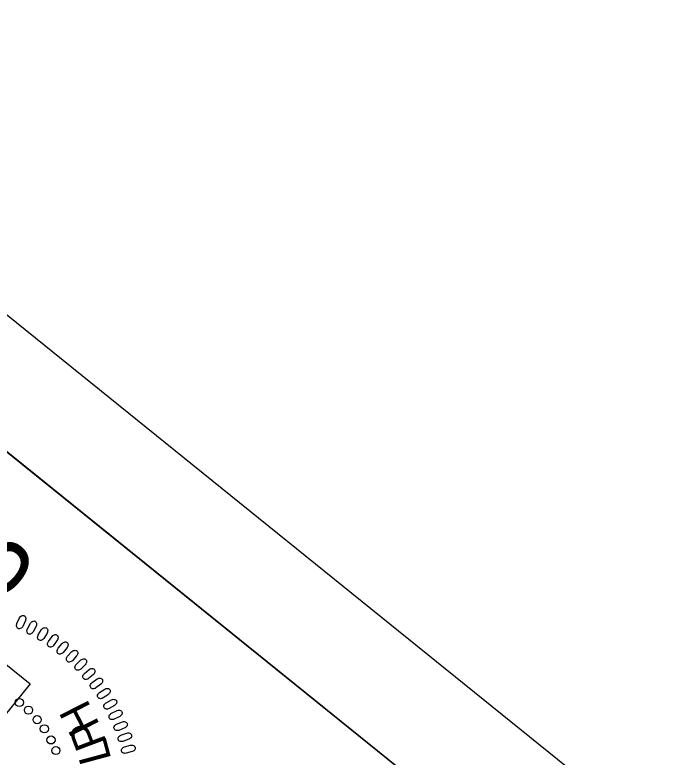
# Model space of a CAD drawing. Extents: x 1487832 to 1490056, y 498345 to 500343.
# Drawn here: x 1488992.8 to 1489096.2, y 500224.6 to 500343.2 of the extents above; entities that cross this region are included whole.
import ezdxf

# ---------------------------------------------------------------- set-up
doc = ezdxf.new("R2010")
doc.units = 0
for name, color, linetype in [('Old_Level_9', 7, 'Continuous'), ('Sheet Plan CELL', 7, 'Continuous'), ('Sheet Plot Border Outside CELL', 7, 'Continuous'), ('Sheet Sticker Incomplete CELL', 7, 'Continuous')]:
    doc.layers.add(name, color=color, linetype=linetype)

msp = doc.modelspace()

# ---------------------------------------------------------------- linework, layer by layer
at = {"layer": 'Old_Level_9'}
for points in [[(1488993.11, 500245.93), (1488993.52, 500246.83), (1488993.62, 500246.98), (1488993.71, 500247.07), (1488993.85, 500247.15), (1488993.96, 500247.2), (1488994.07, 500247.22), (1488994.16, 500247.22), (1488994.25, 500247.2), (1488994.32, 500247.14), (1488994.4, 500247.08), (1488994.46, 500247), (1488994.5, 500246.89), (1488994.52, 500246.81), (1488994.52, 500246.68), (1488994.5, 500246.53), (1488994.47, 500246.4), (1488994.05, 500245.47), (1488993.98, 500245.36), (1488993.9, 500245.27), (1488993.78, 500245.18), (1488993.65, 500245.12), (1488993.55, 500245.09), (1488993.41, 500245.1), (1488993.3, 500245.13), (1488993.2, 500245.21), (1488993.14, 500245.29), (1488993.08, 500245.4), (1488993.05, 500245.57), (1488993.06, 500245.72), (1488993.08, 500245.83)], [(1488994.79, 500245.1), (1488995.26, 500245.98), (1488995.37, 500246.12), (1488995.46, 500246.2), (1488995.61, 500246.28), (1488995.72, 500246.32), (1488995.83, 500246.34), (1488995.92, 500246.33), (1488996.01, 500246.3), (1488996.08, 500246.24), (1488996.15, 500246.17), (1488996.2, 500246.09), (1488996.24, 500245.98), (1488996.25, 500245.9), (1488996.24, 500245.77), (1488996.22, 500245.62), (1488996.17, 500245.49), (1488995.7, 500244.59), (1488995.62, 500244.48), (1488995.53, 500244.4), (1488995.41, 500244.32), (1488995.28, 500244.26), (1488995.18, 500244.24), (1488995.04, 500244.26), (1488994.93, 500244.3), (1488994.83, 500244.39), (1488994.78, 500244.46), (1488994.73, 500244.58), (1488994.71, 500244.75), (1488994.73, 500244.9), (1488994.75, 500245.01)], [(1488996.53, 500244.12), (1488997.06, 500244.96), (1488997.17, 500245.1), (1488997.27, 500245.17), (1488997.42, 500245.24), (1488997.53, 500245.27), (1488997.64, 500245.28), (1488997.73, 500245.26), (1488997.82, 500245.23), (1488997.89, 500245.17), (1488997.96, 500245.1), (1488998, 500245.01), (1488998.03, 500244.9), (1488998.04, 500244.82), (1488998.02, 500244.69), (1488997.99, 500244.54), (1488997.94, 500244.42), (1488997.41, 500243.55), (1488997.32, 500243.44), (1488997.23, 500243.36), (1488997.1, 500243.29), (1488996.96, 500243.24), (1488996.86, 500243.23), (1488996.73, 500243.25), (1488996.62, 500243.31), (1488996.53, 500243.4), (1488996.48, 500243.47), (1488996.43, 500243.6), (1488996.42, 500243.77), (1488996.45, 500243.92), (1488996.49, 500244.02)], [(1488998.15, 500243.07), (1488998.72, 500243.88), (1488998.85, 500244.01), (1488998.95, 500244.07), (1488999.1, 500244.13), (1488999.22, 500244.16), (1488999.33, 500244.16), (1488999.42, 500244.14), (1488999.5, 500244.1), (1488999.57, 500244.03), (1488999.63, 500243.96), (1488999.67, 500243.87), (1488999.7, 500243.75), (1488999.7, 500243.67), (1488999.67, 500243.54), (1488999.63, 500243.4), (1488999.57, 500243.28), (1488998.98, 500242.45), (1488998.89, 500242.34), (1488998.79, 500242.27), (1488998.66, 500242.21), (1488998.52, 500242.17), (1488998.42, 500242.16), (1488998.29, 500242.2), (1488998.18, 500242.25), (1488998.1, 500242.35), (1488998.05, 500242.43), (1488998.02, 500242.56), (1488998.02, 500242.72), (1488998.06, 500242.87), (1488998.1, 500242.97)], [(1488999.69, 500241.98), (1489000.32, 500242.75), (1489000.45, 500242.87), (1489000.56, 500242.93), (1489000.71, 500242.98), (1489000.83, 500243), (1489000.94, 500242.99), (1489001.03, 500242.97), (1489001.11, 500242.92), (1489001.17, 500242.85), (1489001.23, 500242.77), (1489001.27, 500242.68), (1489001.28, 500242.56), (1489001.28, 500242.48), (1489001.24, 500242.36), (1489001.19, 500242.21), (1489001.12, 500242.1), (1489000.49, 500241.3), (1489000.39, 500241.21), (1489000.29, 500241.14), (1489000.15, 500241.09), (1489000.01, 500241.06), (1488999.91, 500241.06), (1488999.78, 500241.1), (1488999.67, 500241.16), (1488999.6, 500241.26), (1488999.56, 500241.35), (1488999.53, 500241.48), (1488999.54, 500241.64), (1488999.59, 500241.79), (1488999.64, 500241.89)], [(1489001.22, 500240.72), (1489001.89, 500241.45), (1489002.03, 500241.56), (1489002.14, 500241.61), (1489002.3, 500241.65), (1489002.42, 500241.67), (1489002.53, 500241.65), (1489002.61, 500241.62), (1489002.69, 500241.57), (1489002.74, 500241.5), (1489002.8, 500241.41), (1489002.83, 500241.32), (1489002.84, 500241.2), (1489002.83, 500241.12), (1489002.79, 500241), (1489002.72, 500240.86), (1489002.65, 500240.75), (1489001.97, 500239.99), (1489001.86, 500239.91), (1489001.76, 500239.85), (1489001.62, 500239.8), (1489001.47, 500239.78), (1489001.37, 500239.78), (1489001.25, 500239.83), (1489001.15, 500239.9), (1489001.08, 500240.01), (1489001.04, 500240.1), (1489001.02, 500240.23), (1489001.04, 500240.39), (1489001.1, 500240.54), (1489001.15, 500240.63)], [(1489002.61, 500239.42), (1489003.32, 500240.11), (1489003.47, 500240.21), (1489003.58, 500240.26), (1489003.75, 500240.29), (1489003.86, 500240.29), (1489003.97, 500240.27), (1489004.05, 500240.24), (1489004.13, 500240.18), (1489004.18, 500240.1), (1489004.23, 500240.02), (1489004.25, 500239.92), (1489004.26, 500239.81), (1489004.24, 500239.73), (1489004.19, 500239.6), (1489004.12, 500239.47), (1489004.04, 500239.36), (1489003.31, 500238.65), (1489003.2, 500238.57), (1489003.09, 500238.52), (1489002.95, 500238.48), (1489002.81, 500238.47), (1489002.7, 500238.48), (1489002.58, 500238.54), (1489002.49, 500238.62), (1489002.43, 500238.73), (1489002.4, 500238.81), (1489002.38, 500238.94), (1489002.41, 500239.11), (1489002.48, 500239.25), (1489002.54, 500239.34)], [(1489003.91, 500237.96), (1489004.67, 500238.6), (1489004.82, 500238.69), (1489004.94, 500238.73), (1489005.1, 500238.75), (1489005.22, 500238.75), (1489005.33, 500238.72), (1489005.41, 500238.68), (1489005.48, 500238.62), (1489005.52, 500238.54), (1489005.57, 500238.45), (1489005.59, 500238.35), (1489005.58, 500238.24), (1489005.56, 500238.16), (1489005.51, 500238.04), (1489005.43, 500237.91), (1489005.34, 500237.81), (1489004.57, 500237.15), (1489004.45, 500237.07), (1489004.34, 500237.03), (1489004.19, 500237), (1489004.05, 500237), (1489003.95, 500237.01), (1489003.83, 500237.08), (1489003.74, 500237.16), (1489003.69, 500237.27), (1489003.66, 500237.36), (1489003.66, 500237.5), (1489003.7, 500237.66), (1489003.77, 500237.79), (1489003.84, 500237.88)], [(1489005.12, 500236.49), (1489005.91, 500237.08), (1489006.07, 500237.16), (1489006.19, 500237.2), (1489006.35, 500237.2), (1489006.47, 500237.19), (1489006.58, 500237.16), (1489006.65, 500237.11), (1489006.72, 500237.05), (1489006.76, 500236.97), (1489006.8, 500236.87), (1489006.81, 500236.78), (1489006.8, 500236.66), (1489006.78, 500236.58), (1489006.71, 500236.47), (1489006.62, 500236.34), (1489006.53, 500236.25), (1489005.72, 500235.64), (1489005.6, 500235.57), (1489005.49, 500235.53), (1489005.34, 500235.51), (1489005.19, 500235.52), (1489005.1, 500235.54), (1489004.98, 500235.61), (1489004.9, 500235.7), (1489004.85, 500235.82), (1489004.83, 500235.91), (1489004.83, 500236.04), (1489004.89, 500236.2), (1489004.97, 500236.33), (1489005.04, 500236.41)], [(1489006.32, 500234.92), (1489007.15, 500235.46), (1489007.32, 500235.54), (1489007.43, 500235.56), (1489007.6, 500235.56), (1489007.72, 500235.54), (1489007.82, 500235.5), (1489007.89, 500235.45), (1489007.96, 500235.38), (1489007.99, 500235.3), (1489008.02, 500235.2), (1489008.03, 500235.11), (1489008.01, 500234.99), (1489007.98, 500234.91), (1489007.91, 500234.8), (1489007.81, 500234.68), (1489007.72, 500234.6), (1489006.87, 500234.04), (1489006.74, 500233.98), (1489006.63, 500233.94), (1489006.48, 500233.93), (1489006.34, 500233.95), (1489006.24, 500233.98), (1489006.13, 500234.06), (1489006.05, 500234.15), (1489006.01, 500234.27), (1489006, 500234.36), (1489006.01, 500234.5), (1489006.07, 500234.65), (1489006.16, 500234.78), (1489006.24, 500234.85)], [(1489007.35, 500233.26), (1489008.21, 500233.75), (1489008.38, 500233.81), (1489008.5, 500233.83), (1489008.67, 500233.82), (1489008.78, 500233.79), (1489008.88, 500233.74), (1489008.95, 500233.69), (1489009.01, 500233.62), (1489009.04, 500233.53), (1489009.07, 500233.43), (1489009.07, 500233.33), (1489009.04, 500233.22), (1489009.01, 500233.15), (1489008.93, 500233.04), (1489008.83, 500232.93), (1489008.72, 500232.85), (1489007.84, 500232.34), (1489007.71, 500232.29), (1489007.59, 500232.26), (1489007.45, 500232.26), (1489007.3, 500232.29), (1489007.21, 500232.32), (1489007.1, 500232.41), (1489007.03, 500232.51), (1489007, 500232.63), (1489006.99, 500232.72), (1489007.01, 500232.85), (1489007.08, 500233), (1489007.18, 500233.12), (1489007.26, 500233.2)], [(1489008.21, 500231.6), (1489009.11, 500232.03), (1489009.28, 500232.08), (1489009.4, 500232.1), (1489009.56, 500232.07), (1489009.68, 500232.04), (1489009.78, 500231.99), (1489009.84, 500231.93), (1489009.9, 500231.85), (1489009.92, 500231.76), (1489009.94, 500231.67), (1489009.94, 500231.57), (1489009.9, 500231.46), (1489009.86, 500231.39), (1489009.78, 500231.28), (1489009.67, 500231.18), (1489009.56, 500231.1), (1489008.65, 500230.65), (1489008.52, 500230.61), (1489008.4, 500230.59), (1489008.25, 500230.6), (1489008.11, 500230.63), (1489008.02, 500230.68), (1489007.92, 500230.77), (1489007.85, 500230.87), (1489007.83, 500230.99), (1489007.83, 500231.09), (1489007.85, 500231.22), (1489007.93, 500231.36), (1489008.04, 500231.48), (1489008.13, 500231.54)], [(1489009.04, 500229.85), (1489009.96, 500230.22), (1489010.13, 500230.26), (1489010.25, 500230.27), (1489010.41, 500230.24), (1489010.53, 500230.2), (1489010.62, 500230.14), (1489010.68, 500230.07), (1489010.73, 500229.99), (1489010.75, 500229.9), (1489010.76, 500229.8), (1489010.75, 500229.71), (1489010.71, 500229.6), (1489010.67, 500229.53), (1489010.58, 500229.43), (1489010.46, 500229.33), (1489010.35, 500229.27), (1489009.41, 500228.87), (1489009.28, 500228.84), (1489009.16, 500228.83), (1489009.01, 500228.85), (1489008.87, 500228.89), (1489008.78, 500228.94), (1489008.69, 500229.04), (1489008.63, 500229.14), (1489008.61, 500229.27), (1489008.62, 500229.36), (1489008.65, 500229.49), (1489008.74, 500229.63), (1489008.86, 500229.73), (1489008.94, 500229.8)], [(1489009.73, 500228.11), (1489010.67, 500228.43), (1489010.85, 500228.45), (1489010.97, 500228.45), (1489011.13, 500228.41), (1489011.24, 500228.36), (1489011.33, 500228.3), (1489011.38, 500228.23), (1489011.43, 500228.15), (1489011.44, 500228.06), (1489011.45, 500227.96), (1489011.43, 500227.86), (1489011.38, 500227.75), (1489011.34, 500227.69), (1489011.24, 500227.6), (1489011.12, 500227.5), (1489011, 500227.45), (1489010.04, 500227.11), (1489009.9, 500227.09), (1489009.78, 500227.09), (1489009.64, 500227.11), (1489009.5, 500227.16), (1489009.42, 500227.22), (1489009.33, 500227.32), (1489009.27, 500227.43), (1489009.27, 500227.56), (1489009.28, 500227.65), (1489009.32, 500227.77), (1489009.42, 500227.91), (1489009.54, 500228.01), (1489009.63, 500228.06)], [(1489010.31, 500226.23), (1489011.27, 500226.48), (1489011.45, 500226.5), (1489011.57, 500226.49), (1489011.72, 500226.44), (1489011.83, 500226.39), (1489011.91, 500226.31), (1489011.97, 500226.24), (1489012.01, 500226.16), (1489012.01, 500226.07), (1489012.02, 500225.97), (1489011.99, 500225.87), (1489011.94, 500225.77), (1489011.89, 500225.7), (1489011.78, 500225.62), (1489011.66, 500225.54), (1489011.54, 500225.48), (1489010.56, 500225.21), (1489010.42, 500225.19), (1489010.3, 500225.2), (1489010.16, 500225.24), (1489010.02, 500225.3), (1489009.94, 500225.35), (1489009.86, 500225.46), (1489009.81, 500225.58), (1489009.81, 500225.7), (1489009.83, 500225.79), (1489009.88, 500225.92), (1489009.99, 500226.04), (1489010.11, 500226.14), (1489010.21, 500226.19)]]:
    msp.add_lwpolyline(points, close=True, dxfattribs=at)
for centre in [(1488993.5, 500233.32), (1488994.97, 500232.1), (1488996.35, 500230.57), (1488997.49, 500229.11), (1488998.56, 500227.34), (1488999.34, 500225.64)]:
    msp.add_circle(centre, 0.649, dxfattribs=at)
at = {"layer": 'Sheet Plan CELL'}
for points in [[(1488938.86, 500315.83), (1487997.21, 499148.18), (1488814.55, 498489.05), (1489756.18, 499656.68)], [(1488905.31, 500214.39), (1488968.07, 500292.23), (1489055.66, 500221.61), (1488992.89, 500143.76)]]:
    msp.add_lwpolyline(points, close=True, dxfattribs=at)
at = {"layer": 'Sheet Plot Border Outside CELL'}
msp.add_lwpolyline([(1488727.56, 498345.32), (1489784.38, 499655.78), (1488932.01, 500343.17), (1487875.19, 499032.7)], close=True, dxfattribs=at)
at = {"layer": 'Sheet Sticker Incomplete CELL'}
msp.add_lwpolyline([(1488902.95, 500121.87), (1488884.66, 500136.62), (1488976.94, 500251.05), (1488995.23, 500236.3)], close=True, dxfattribs=at)

# ---------------------------------------------------------------- texts
at = {"layer": 'Old_Level_9'}
for s, rotation, p in [('H', 116.8747, (1489006.42, 500229.73)), ('P', 110.6136, (1489007.52, 500226.87)), ('L', 105.0875, (1489008.23, 500224.25))]:
    msp.add_text(s, height=5.05, rotation=rotation, dxfattribs=at).set_placement(p)
at = {"layer": 'Sheet Sticker Incomplete CELL'}
msp.add_text('INCOMPLETE PLANS', height=11.52, rotation=51.1156, dxfattribs=at).set_placement((1488899.47, 500136.18))

doc.saveas('drawing.dxf')
